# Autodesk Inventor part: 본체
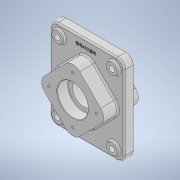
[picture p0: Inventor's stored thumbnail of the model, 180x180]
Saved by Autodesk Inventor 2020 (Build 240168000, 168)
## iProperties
Created: 2021-07
Part Number: 본체
Material: 일반
Document SubType Name: Modeling
Designer: Owner
Density: 1 g/cm^3
Appearance: 기본값
Mass: 808.161 g
Surface Area: 960.878 cm^2
Volume: 808.161 cm^3
Author: Owner
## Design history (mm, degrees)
sketch "스케치1"
  geometry: L1 (-75, 90)-(75, 90); L2 (75, 90)-(75, -90); L3 (75, -90)-(-75, -90); L4 (-75, -90)-(-75, 90); L5 (-75, 90)-(75, -90); L6 (75, 90)-(-75, -90); 1 further point
  constraints: 12 end point, 2 midpoint, 2 parallel, 1 horizontal, 1 perpendicular
  dimensions: "d0" = 150 distance of L2.end L3.end; "d1" = 180 distance of L1.end L2.end
extrude "돌출1" new body sketch "스케치1" stored distance "d2" = 18; taper "d3" = 0 deg
sketch "스케치2"
  geometry: L1 (75, 90)-(-75, 90) reference; L2 (-75, 90)-(-75, -90) reference; L3 (-75, -90)-(75, -90) reference; L4 (75, -90)-(75, 90) reference; L5 (0, 70.711)-(-70.711, 0); L6 (-70.711, 0)-(0, -70.711); L7 (0, -70.711)-(70.711, 0); L8 (70.711, 0)-(0, 70.711); L9 (0, 70.711)-(0, -70.711); L10 (-70.711, 0)-(70.711, 0); 1 further point
  constraints: 12 end point, 2 midpoint, 2 parallel, 1 perpendicular, 1 vertical
  dimensions: "d4" = 100 distance of L5.start L5.end; "d5" = 100 distance of L6.end L5.end
extrude "돌출2" join sketch "스케치2" distance "d6" = 29; taper "d7" = 0 deg
sketch "스케치3"
  geometry: L1 (75, 90)-(-75, 90) reference; L2 (-75, 90)-(-75, -90) reference; L3 (-75, -90)-(75, -90) reference; L4 (75, -90)-(75, 90) reference; L5 (0, 70.711)-(-70.711, 0); L6 (-70.711, 0)-(0, -70.711); L7 (0, -70.711)-(70.711, 0); L8 (70.711, 0)-(0, 70.711); L9 (0, 70.711)-(0, -70.711); L10 (-70.711, 0)-(70.711, 0); 1 further point
  constraints: 12 end point, 2 midpoint, 2 parallel, 2 perpendicular, 1 vertical
  dimensions: "d8" = 100 distance of L6.end L5.end
extrude "돌출3" join sketch "스케치3" distance "d9" = 23; taper "d10" = 0 deg
sketch "스케치4"
  geometry: C1 r 31 at (0, 0); 1 further point
  constraints: 1 centre point, 1 coincident
  dimensions: "d11" = 62 diameter of C1
hole "구멍1" sketch "스케치4" at (0, 0) diameter "d12" = 45; stored, may be unused: countersink angle "d16" = 90 deg, drill point angle "d18" = 118 deg; dims "d13" = 6, "d14" = 62, "d15" = 22, "d17" = 8
sketch "스케치5" dims "d19" = 96
  geometry: 3 further points
  constraints: 2 vertical alignment, 1 coincident, 2 other
hole "구멍2" sketch "스케치5" at (0, 48) diameter "d20" = 4.917; stored, may be unused: countersink angle "d24" = 90 deg, drill point angle "d26" = 0 deg; dims "d21" = 10, "d22" = 62, "d23" = 22, "d25" = 13
node "작업 평면1"
fillet "모깎기1" dims "d31" = 15
sketch "스케치6"
  geometry: L1 (-75, 75)-(-75, -75) reference; L2 (-60, -90)-(60, -90) reference; L3 (75, -75)-(75, 75) reference; L4 (60, 90)-(-60, 90) reference; L5 (0, 70.711)-(70.711, 0) reference; L6 (70.711, 0)-(0, -70.711) reference; L7 (0, -70.711)-(-70.711, 0) reference; L8 (-70.711, 0)-(0, 70.711) reference; L9 (-55, 70)-(55, 70); C1 r 11 at (-55, 70); C2 r 11 at (55, 70); A1 r 15 centre (-60, 75) between (-60, 90) and (-75, 75) reference; A2 r 15 centre (-60, -75) between (-75, -75) and (-60, -90) reference; A3 r 15 centre (60, -75) between (60, -90) and (75, -75) reference; A4 r 15 centre (60, 75) between (75, 75) and (60, 90) reference; 2 further points
  constraints: 2 centre point, 2 end point, 1 equal radius, 1 horizontal, 1 midpoint, 1 vertical alignment
  dimensions: "d37" = 22 diameter of C1; "d38" = 110 distance of L9.start L9.end; "d39" = 70 distance from line of point (0, 0) L9
extrude "돌출4" join sketch "스케치6" distance "d40" = 5; taper "d41" = 0 deg
sketch "스케치7"
  geometry: C1 r 11 at (0, 0) reference; C2 r 11 at (110, 0) reference; 3 further points
  constraints: 2 coincident
hole "구멍3" sketch "스케치7" at (0, 0), (110, 0) diameter "d42" = 11; stored, may be unused: countersink angle "d46" = 90 deg, drill point angle "d48" = 0 deg; dims "d43" = 11, "d44" = 22, "d45" = 18, "d47" = 29.3
sketch "스케치8"
  geometry: 1 further point
fillet "모깎기2" dims "d49" = 20
fillet "모깎기3" dims "d50" = 3
fillet "모깎기4" dims "d51" = 20
fillet "모깎기5" dims "d52" = 3
fillet "모깎기6" dims "d53" = 3
sketch "스케치9"
  geometry: L1 (60, 90)-(-60, 90) reference; 2 further points
  constraints: 1 other
  dimensions: "d56" = 15 distance from line of L1 point (-2.409, 75)
feature "엠보싱1" sketch "스케치9" dims "d0" = 150, "d1" = 180, "d54" = 0.5, "d55" = 0
chamfer "모따기1" distance "d57" = 1; stored, may be unused: second distance "d58" = 2, angle "d59" = 45 deg
chamfer "모따기2" distance "d60" = 1; stored, may be unused: second distance "d61" = 2, angle "d62" = 45 deg
sketch "스케치10"
  geometry: L1 (-56.569, -14.142)-(-14.142, -56.569) reference; L2 (14.142, -56.569)-(56.569, -14.142) reference; L3 (56.569, 14.142)-(14.142, 56.569) reference; L4 (-14.142, 56.569)-(-56.569, 14.142) reference; C1 r 2.458 at (-48, 0) reference; C2 r 2.458 at (0, -48) reference; C3 r 2.458 at (48, 0) reference; C4 r 2.458 at (0, 48) reference; C5 r 23.5 at (0, 0) reference; C6 r 31 at (0, 0); A1 r 20 centre (-42.426, 0) between (-56.569, 14.142) and (-56.569, -14.142) reference; A2 r 20 centre (0, -42.426) between (-14.142, -56.569) and (14.142, -56.569) reference; A3 r 20 centre (42.426, 0) between (56.569, -14.142) and (56.569, 14.142) reference; A4 r 20 centre (0, 42.426) between (14.142, 56.569) and (-14.142, 56.569) reference; 1 further point
  constraints: 1 centre point, 1 coincident
  dimensions: "d63" = 62 diameter of C6
hole "구멍4" sketch "스케치10" at (0, 0) diameter "d64" = 45; stored, may be unused: countersink angle "d68" = 90 deg, drill point angle "d70" = 0 deg; dims "d65" = 11, "d66" = 62, "d67" = 22, "d69" = 29.3
chamfer "모따기3" distance "d71" = 1; stored, may be unused: second distance "d72" = 2, angle "d73" = 45 deg
fillet "모깎기7" dims "d74" = 3
node "솔리드1"
pattern_circular "원형 패턴1" dims angle "d28" = 360 deg
mirror "미러1"
mirror "미러2"
node "투영된 루프1"
node "투영된 루프2"
node "투영된 루프3"
node "투영된 루프4"
feature "A9D066F2-1C7D-4E18-AEED-F7BC21143FA4" dims "d12" = 45, "d13" = 6, "d14" = 62, "d15" = 22, "d16" = 90 deg, "d17" = 8, "d18" = 118 deg
other parameters: "d30" = -35
